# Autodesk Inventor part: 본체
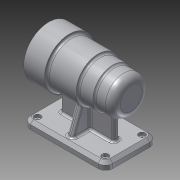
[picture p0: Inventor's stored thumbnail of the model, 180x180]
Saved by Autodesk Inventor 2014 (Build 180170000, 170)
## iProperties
Created: 2016-06
Part Number: 본체
Material: Aluminum 6061
Document SubType Name: Modeling
Designer: user
Density: 2.71 g/cm^3
Appearance: Aluminum - Flat
Mass: 673.031 g
Surface Area: 650.376 cm^2
Volume: 248.351 cm^3
Author: user
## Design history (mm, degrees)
sketch "Sketch1"
  geometry: L1 (-56, 35)-(56, 35); L2 (56, 35)-(56, -35); L3 (56, -35)-(-56, -35); L4 (-56, -35)-(-56, 35); 3 further points
  constraints: 8 end point, 2 midpoint, 2 parallel, 1 horizontal, 1 horizontal alignment, 1 perpendicular, 1 vertical alignment
  dimensions: "d0" = 112 distance of L2.end L3.end; "d1" = 70 distance of L1.end L2.end
extrude "Extrusion1" new body sketch "Sketch1" distance "d2" = 10; taper "d3" = 0 deg
fillet "Fillet1" dims "d4" = 10
workplane "Work Plane1"
sketch "Sketch2"
  geometry: L1 (25, 0)-(-25, 0) reference; C1 r 25 at (0, 70); 1 further point
  constraints: 1 centre point
  dimensions: "d6" = 50 diameter of C1; "d7" = 70 distance from line of L1 C1.centre
extrude "Extrusion2" join sketch "Sketch2" distance "d8" = 25; taper "d9" = 0 deg
sketch "Sketch3"
  geometry: C1 r 25 at (0, 0) reference; C2 r 27 at (0, 0); 1 further point
  constraints: 1 centre point, 1 coincident
  dimensions: "d10" = 54 diameter of C2
extrude "Extrusion3" join sketch "Sketch3" distance "d11" = 20; taper "d12" = 0 deg
sketch "Sketch4"
  geometry: C1 r 27 at (0, 0) reference; C2 r 30 at (0, 0); 1 further point
  constraints: 1 centre point, 1 coincident
  dimensions: "d13" = 60 diameter of C2
extrude "Extrusion4" join sketch "Sketch4" distance "d14" = 39; taper "d15" = 0 deg
sketch "Sketch5"
  geometry: C1 r 30 at (0, 0) reference; C2 r 34 at (0, 0); 1 further point
  constraints: 1 centre point, 1 coincident
  dimensions: "d16" = 68 diameter of C2
extrude "Extrusion5" join sketch "Sketch5" distance "d17" = 28; taper "d18" = 0 deg
workplane "Work Plane2"
sketch "Sketch6"
  geometry: L1 (36, -4)-(-36, -4); L2 (-36, -4)-(-36, 4); L3 (-36, 4)-(36, 4); L4 (36, 4)-(36, -4); 3 further points
  constraints: 8 end point, 2 midpoint, 2 parallel, 1 horizontal, 1 horizontal alignment, 1 perpendicular, 1 vertical alignment
  dimensions: "d20" = 8 distance of L1.end L2.end; "d21" = 72 distance of L1.start L1.end
extrude "Extrusion6" join sketch "Sketch6" stored distance "d22" = 28; taper "d23" = 0 deg
chamfer "Chamfer1" distance "d24" = 4; stored, may be unused: second distance "d25" = 2, angle "d26" = 45 deg
sketch "Sketch7"
  geometry: C1 r 34 at (0, 0) reference; C2 r 21 at (0, 0); 1 further point
  constraints: 1 centre point, 1 coincident
  dimensions: "d27" = 42 diameter of C2
extrude "Extrusion7" cut sketch "Sketch7" distance "d28" = 15; taper "d29" = 0 deg
sketch "Sketch8"
  geometry: C1 r 21 at (0, 0) reference; C2 r 24 at (0, 0); 1 further point
  constraints: 1 centre point, 1 coincident
  dimensions: "d30" = 48 diameter of C2
extrude "Extrusion8" cut sketch "Sketch8" distance "d31" = 54; taper "d32" = 0 deg
sketch "Sketch9"
  geometry: C1 r 24 at (0, 0) reference; C2 r 21 at (0, 0); 1 further point
  constraints: 1 centre point, 1 coincident
  dimensions: "d33" = 42 diameter of C2
extrude "Extrusion9" cut sketch "Sketch9" distance "d34" = 12; taper "d35" = 0 deg
sketch "Sketch10"
  geometry: C1 r 21 at (0, 0) reference; C2 r 17.5 at (0, 0); 1 further point
  constraints: 1 centre point, 1 coincident
  dimensions: "d36" = 35 diameter of C2
extrude "Extrusion10" cut sketch "Sketch10" distance "d37" = 18; taper "d38" = 0 deg
sketch "Sketch11"
  geometry: C1 r 17.5 at (0, 0) reference; C2 r 16 at (0, 0); 1 further point
  constraints: 1 centre point, 1 coincident
  dimensions: "d39" = 32 diameter of C2
extrude "Extrusion11" cut sketch "Sketch11" distance "d40" = 4; taper "d41" = 0 deg
sketch "Sketch12"
  geometry: C1 r 16 at (0, 0) reference; C2 r 10.5 at (0, 0); 1 further point
  constraints: 1 centre point, 1 coincident
  dimensions: "d42" = 21 diameter of C2
extrude "Extrusion12" cut sketch "Sketch12" distance "d43" = 3; taper "d44" = 0 deg
fillet "Fillet2" dims "d45" = 10
fillet "Fillet3" dims "d46" = 3
fillet "Fillet4" dims "d47" = 0.3
fillet "Fillet5" dims "d48" = 3
chamfer "Chamfer2" distance "d49" = 1; stored, may be unused: second distance "d50" = 2, angle "d51" = 45 deg
sketch "Sketch13"
  geometry: C1 r 34 at (0, 0) reference; 2 further points
  dimensions: "d52" = 26 distance of C1.centre point (26, 0)
hole "Hole1" sketch "Sketch13" at (26, 0) diameter "d53" = 3.242; stored, may be unused: countersink angle "d57" = 90 deg, drill point angle "d59" = 118 deg; dims "d54" = 8, "d55" = 4, "d56" = 2, "d58" = 11
pattern_circular "Circular Pattern1" dims angle "d61" = 360 deg
sketch "Sketch14"
  geometry: L1 (56, -25)-(56, 25) reference; 3 further points
  dimensions: "d63" = 50 distance of point (46, 24.728) point (46, -25.272); "d64" = 10 distance from line of point (46, -25.272) L1; "d65" = 10 distance from line of L1 point (46, 24.728)
hole "Hole2" sketch "Sketch14" at (46, -25.272), (46, 24.728) diameter "d66" = 5; stored, may be unused: countersink angle "d70" = 90 deg, drill point angle "d72" = 0 deg; dims "d67" = 8, "d68" = 9, "d69" = 4, "d71" = 10
mirror "Mirror1"
sketch "Sketch15"
  geometry: L1 (15.509, 44.32)-(28, 10); L2 (-25, 10)-(25, 10) reference; L3 (25, 10)-(31, 10) reference; A1 r 30 centre (0, 70) between (4, 40.268) and (-4, 40.268) reference; A2 r 30 centre (0, 70) between (4, 40.268) and (-4, 40.268) reference; A3 r 30 centre (0, 70) between (4, 40.268) and (-4, 40.268) reference; 2 further points
  constraints: 2 end point, 2 point on circle, 1 point on line
  dimensions: "d73" = 7 horizontal distance of point (35, 0) L1.end; "d74" = 110 deg angle of L3 L1
feature "Rib1" sketch "Sketch15" dims "d75" = 8, "d76" = 8, "d77" = 0, "d78" = 0, "d79" = 1, "d80" = 1
mirror "Mirror2"
fillet "Fillet6" dims "d81" = 3
workplane "Work Plane3"
sketch "Sketch16"
  geometry: L1 (-7.909, 72.251)-(23.909, 72.251); L2 (23.909, 72.251)-(23.909, 67.749); L3 (23.909, 67.749)-(-7.909, 67.749); L4 (-7.909, 67.749)-(-7.909, 72.251); L5 (46, 0)-(-46, 0) reference; L6 (56, 36)-(56, 104) reference; 4 further points
  constraints: 2 midpoint, 1 horizontal alignment, 1 vertical alignment, 2 other
  dimensions: "d87" = 70 distance from line of L5 point (8, 70); "d88" = 48 distance from line of L6 point (8, 70)
emboss "Emboss1" sketch "Sketch16" dims "d89" = 0.5, "d90" = 0
fillet "Fillet8" dims "d91" = 3
fillet "Fillet9" dims "d92" = 3
body "Solid1"
node "Projected Loop1"
other parameters: "d5" = 56, "d19" = -56
